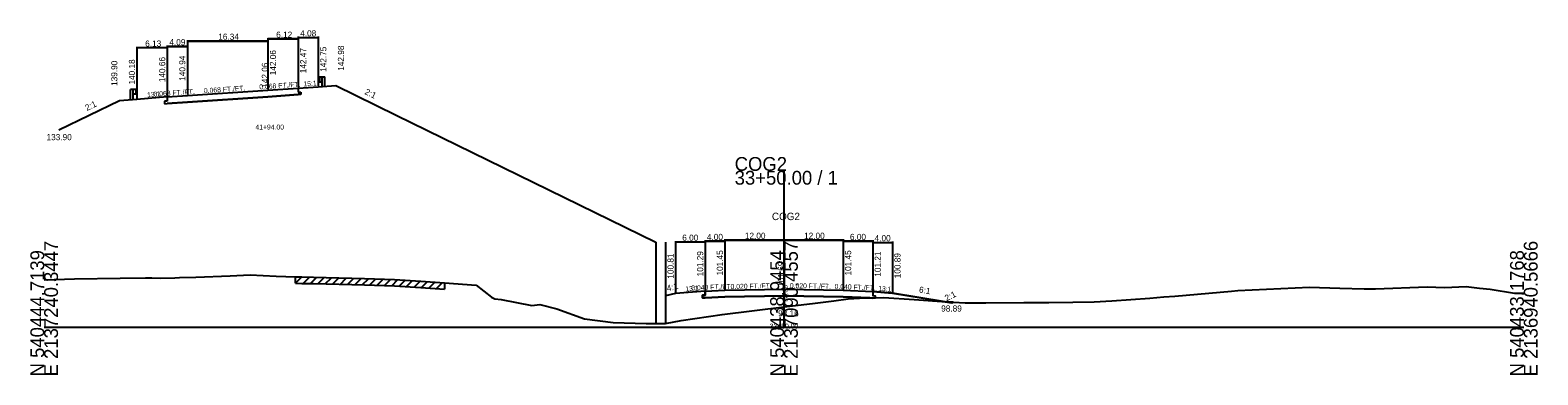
# Model space of a CAD drawing. Extents: x -13397 to 2303, y -10 to 39059.
# Drawn here: x 997.2 to 1302.8, y 6990.3 to 7060.2 of the extents above; entities that cross this region are included whole.
import ezdxf

# ---------------------------------------------------------------- set-up
doc = ezdxf.new("R2010")
doc.units = 0
for name, color, linetype in [('Level 20', 7, 'Continuous'), ('Level 5', 7, 'Continuous'), ('Level 53', 7, 'Continuous'), ('Level 54', 7, 'Continuous'), ('Level 55', 7, 'Continuous'), ('Level 7', 7, 'Continuous'), ('RD_GPK_XS_Cell', 7, 'Continuous'), ('RD_XS_EwShp', 7, 'Continuous'), ('RD_XS_ExGround', 7, 'Continuous'), ('RD_XS_ExPaveRet', 7, 'Continuous'), ('RD_XS_MedBWall', 7, 'Continuous'), ('RD_XS_Pave', 7, 'Continuous'), ('RD_XS_TX_Baseline', 7, 'Continuous'), ('RD_XS_TX_Elev_EX', 7, 'Continuous'), ('RD_XS_TX_Elev_PR', 7, 'Continuous'), ('RD_XS_TX_Station', 7, 'Continuous')]:
    doc.layers.add(name, color=color, linetype=linetype)

msp = doc.modelspace()

# ---------------------------------------------------------------- linework, layer by layer
at = {"layer": 'Level 20'}
for p, q in [((1029.03, 7058.21), (1029.03, 7047.14)), ((1029.03, 7058.21), (1029.03, 7047.14)), ((1029.03, 7058.21), (1029.03, 7047.14)), ((1029.03, 7058.21), (1029.03, 7047.14)), ((1045.37, 7058.62), (1045.37, 7048.26)), ((1045.37, 7058.62), (1045.37, 7048.26)), ((1045.37, 7058.62), (1045.37, 7048.26)), ((1045.37, 7058.42), (1051.5, 7058.42)), ((1051.5, 7058.42), (1045.37, 7058.42)), ((1051.5, 7058.42), (1045.37, 7058.42)), ((1045.37, 7058.21), (1045.37, 7048.26)), ((1045.37, 7058.21), (1045.37, 7048.26)), ((1045.37, 7058.21), (1045.37, 7048.26)), ((1045.37, 7058.21), (1045.37, 7048.26)), ((1051.5, 7058.9), (1051.5, 7048.67)), ((1051.5, 7058.7), (1055.58, 7058.7)), ((1051.5, 7058.62), (1051.5, 7048.67)), ((1051.5, 7058.62), (1051.5, 7048.67)), ((1051.5, 7058.62), (1051.5, 7048.67)), ((1055.58, 7058.9), (1055.58, 7048.95)), ((1018.81, 7056.81), (1018.81, 7046.38)), ((1024.94, 7056.61), (1018.81, 7056.61)), ((1024.94, 7057.09), (1024.94, 7046.86)), ((1024.94, 7057.09), (1024.94, 7046.86)), ((1024.94, 7057.09), (1024.94, 7046.86)), ((1024.94, 7056.89), (1029.03, 7056.89)), ((1024.94, 7056.89), (1029.03, 7056.89)), ((1029.03, 7056.89), (1024.94, 7056.89)), ((1024.94, 7056.81), (1024.94, 7046.86)), ((1029.03, 7058.01), (1045.37, 7058.01)), ((1029.03, 7058.01), (1045.37, 7058.01)), ((1045.37, 7058.01), (1029.03, 7058.01)), ((1045.37, 7058.01), (1029.03, 7058.01)), ((1029.03, 7057.09), (1029.03, 7047.14)), ((1029.03, 7057.09), (1029.03, 7047.14)), ((1029.03, 7057.09), (1029.03, 7047.14)), ((1055.6, 7050.56), (1055.72, 7050.65)), ((1055.6, 7050.46), (1055.72, 7050.37)), ((1055.6, 7050.03), (1055.72, 7050.12)), ((1055.6, 7049.93), (1055.72, 7049.84)), ((1055.73, 7050.66), (1055.8, 7050.67)), ((1055.73, 7050.32), (1055.73, 7050.17)), ((1055.73, 7049.83), (1055.8, 7049.82)), ((1055.8, 7050.73), (1055.8, 7049.76)), ((1055.8, 7050.73), (1056.36, 7050.73)), ((1055.8, 7049.76), (1056.36, 7049.76)), ((1056.36, 7048.75), (1056.36, 7050.73)), ((1056.36, 7050.73), (1056.92, 7050.73)), ((1056.92, 7048.75), (1056.92, 7050.73)), ((1018.81, 7046.18), (1015.24, 7045.9)), ((1017.48, 7046.18), (1017.48, 7048.17)), ((1018.03, 7048.17), (1017.48, 7048.17)), ((1018.03, 7046.18), (1018.03, 7048.17)), ((1018.59, 7048.17), (1018.03, 7048.17)), ((1018.59, 7047.2), (1018.03, 7047.2)), ((1018.59, 7048.17), (1018.59, 7047.2)), ((1018.66, 7048.1), (1018.59, 7048.11)), ((1018.66, 7047.27), (1018.59, 7047.26)), ((1018.66, 7047.76), (1018.66, 7047.61)), ((1018.79, 7048), (1018.68, 7048.09)), ((1018.79, 7047.9), (1018.68, 7047.81)), ((1018.79, 7047.47), (1018.68, 7047.56)), ((1018.79, 7047.37), (1018.68, 7047.28)), ((1024.94, 7046.66), (1018.81, 7046.18)), ((1024.94, 7046.66), (1029.03, 7046.94)), ((1024.94, 7046.66), (1024.94, 7045.83)), ((1029.03, 7046.94), (1045.37, 7048.06)), ((1045.37, 7046.72), (1029.03, 7045.61)), ((1045.37, 7046.72), (1029.03, 7045.61)), ((1029.03, 7045.61), (1045.37, 7046.72)), ((1029.03, 7045.61), (1045.37, 7046.72)), ((1045.37, 7048.06), (1051.5, 7048.47)), ((1051.5, 7047.14), (1045.37, 7046.72)), ((1045.37, 7046.72), (1051.5, 7047.14)), ((1045.37, 7046.72), (1051.5, 7047.14)), ((1051.5, 7048.47), (1055.58, 7048.75)), ((1051.5, 7048.47), (1051.5, 7047.64)), ((1051.5, 7047.64), (1052.01, 7047.67)), ((1052.01, 7047.17), (1051.5, 7047.14)), ((1052.01, 7047.67), (1052.01, 7047.17)), ((1055.58, 7048.75), (1059.15, 7048.98)), ((1059.15, 7048.98), (1071.4, 7042.98)), ((1015.24, 7045.9), (1002.98, 7039.9)), ((1024.94, 7045.83), (1024.43, 7045.8)), ((1024.43, 7045.8), (1024.43, 7045.3)), ((1024.43, 7045.3), (1024.94, 7045.33)), ((1029.03, 7045.61), (1024.94, 7045.33)), ((1029.03, 7045.61), (1024.94, 7045.33)), ((1024.94, 7045.33), (1029.03, 7045.61)), ((1071.4, 7042.98), (1124, 7017.22))]:
    msp.add_line(p, q, dxfattribs=at)
for centre, radius, start, end in [((1055.64, 7050.51), 0.0651, 129.0336, 230.9663), ((1055.64, 7049.98), 0.0651, 129.0336, 230.9663), ((1055.67, 7050.17), 0.0651, 302.9895, 0), ((1055.73, 7050.63), 0.026, 90, 129.0505), ((1055.67, 7050.32), 0.0651, 0, 45), ((1055.73, 7049.86), 0.026, 230.9496, 270), ((1018.66, 7048.07), 0.026, 50.9495, 90), ((1018.72, 7047.76), 0.0651, 135, 180), ((1018.72, 7047.61), 0.0651, 180, 237.0105), ((1018.66, 7047.3), 0.026, 270, 309.0504), ((1018.75, 7047.95), 0.0651, 309.0337, 50.9664), ((1018.75, 7047.42), 0.0651, 309.0337, 50.9664)]:
    msp.add_arc(centre, radius, start, end, dxfattribs=at)
at = {"layer": 'Level 5'}
for p, q in [((1134, 7006.46), (1133.5, 7006.44)), ((1133.5, 7006.44), (1133.5, 7005.94)), ((1134, 7007.29), (1134, 7006.46)), ((1150, 7006.36), (1138, 7006.12)), ((1150, 7006.36), (1138, 7006.12)), ((1150, 7006.36), (1138, 7006.12)), ((1138, 7006.12), (1150, 7006.36)), ((1138, 7006.12), (1150, 7006.36)), ((1162, 7006.12), (1150, 7006.36)), ((1162, 7006.12), (1150, 7006.36)), ((1150, 7006.36), (1162, 7006.12)), ((1150, 7006.36), (1162, 7006.12)), ((1150, 7006.36), (1162, 7006.12)), ((1168, 7007.21), (1168, 7006.38)), ((1168, 7006.38), (1168.5, 7006.36)), ((1168.5, 7006.36), (1168.5, 7005.86)), ((1133.5, 7005.94), (1134, 7005.96)), ((1138, 7006.12), (1134, 7005.96)), ((1138, 7006.12), (1134, 7005.96)), ((1138, 7006.12), (1134, 7005.96)), ((1134, 7005.96), (1138, 7006.12)), ((1168, 7005.88), (1162, 7006.12)), ((1162, 7006.12), (1168, 7005.88)), ((1162, 7006.12), (1168, 7005.88)), ((1162, 7006.12), (1168, 7005.88)), ((1168.5, 7005.86), (1168, 7005.88))]:
    msp.add_line(p, q, dxfattribs=at)
at = {"layer": 'Level 54'}
for p, q in [((1128, 7017.44), (1128, 7007.01)), ((1134, 7017.24), (1128, 7017.24)), ((1134, 7017.6), (1134, 7007.49)), ((1134, 7017.6), (1134, 7007.49)), ((1134, 7017.6), (1134, 7007.49)), ((1134, 7017.6), (1134, 7007.49)), ((1134, 7017.44), (1134, 7007.49)), ((1134, 7017.4), (1138, 7017.4)), ((1134, 7017.4), (1138, 7017.4)), ((1134, 7017.4), (1138, 7017.4)), ((1138, 7017.4), (1134, 7017.4)), ((1138, 7017.84), (1138, 7007.65)), ((1138, 7017.84), (1138, 7007.65)), ((1138, 7017.84), (1138, 7007.65)), ((1138, 7017.84), (1138, 7007.65)), ((1138, 7017.84), (1138, 7007.65)), ((1138, 7017.64), (1150, 7017.64)), ((1138, 7017.64), (1150, 7017.64)), ((1138, 7017.64), (1150, 7017.64)), ((1150, 7017.64), (1138, 7017.64)), ((1150, 7017.64), (1138, 7017.64)), ((1138, 7017.6), (1138, 7007.65)), ((1138, 7017.6), (1138, 7007.65)), ((1138, 7017.6), (1138, 7007.65)), ((1138, 7017.6), (1138, 7007.65)), ((1150, 7017.84), (1150, 7007.89)), ((1150, 7017.84), (1150, 7007.89)), ((1150, 7017.84), (1150, 7007.89)), ((1150, 7017.84), (1150, 7007.89)), ((1150, 7017.84), (1150, 7007.89)), ((1150, 7017.84), (1150, 7007.89)), ((1150, 7017.84), (1150, 7007.89)), ((1150, 7017.84), (1150, 7007.89)), ((1150, 7017.84), (1150, 7007.89)), ((1150, 7017.84), (1150, 7007.89)), ((1150, 7017.64), (1162, 7017.64)), ((1150, 7017.64), (1162, 7017.64)), ((1162, 7017.64), (1150, 7017.64)), ((1162, 7017.64), (1150, 7017.64)), ((1162, 7017.64), (1150, 7017.64)), ((1162, 7017.84), (1162, 7007.65)), ((1162, 7017.84), (1162, 7007.65)), ((1162, 7017.84), (1162, 7007.65)), ((1162, 7017.84), (1162, 7007.65)), ((1162, 7017.84), (1162, 7007.65)), ((1162, 7017.6), (1162, 7007.65)), ((1162, 7017.6), (1162, 7007.65)), ((1162, 7017.6), (1162, 7007.65)), ((1162, 7017.6), (1162, 7007.65)), ((1162, 7017.4), (1168, 7017.4)), ((1168, 7017.4), (1162, 7017.4)), ((1168, 7017.4), (1162, 7017.4)), ((1168, 7017.4), (1162, 7017.4)), ((1168, 7017.6), (1168, 7007.41)), ((1168, 7017.6), (1168, 7007.41)), ((1168, 7017.6), (1168, 7007.41)), ((1168, 7017.6), (1168, 7007.41)), ((1168, 7017.36), (1168, 7007.41)), ((1168, 7017.16), (1172, 7017.16)), ((1172, 7017.36), (1172, 7007.09))]:
    msp.add_line(p, q, dxfattribs=at)
at = {"layer": 'Level 7'}
for p, q in [((1128, 7006.81), (1126, 7006.31)), ((1126, 7006.31), (1126, 7000.71)), ((1134, 7007.29), (1128, 7006.81)), ((1168, 7007.21), (1172, 7006.89)), ((1172, 7006.89), (1184, 7004.89)), ((1184, 7004.89), (1184.27, 7005.03))]:
    msp.add_line(p, q, dxfattribs=at)
at = {"layer": 'RD_GPK_XS_Cell'}
for p, q in [((1150, 7000), (1150, 7031.68)), ((1000, 7000), (1150, 7000)), ((1150, 7000), (1300, 7000))]:
    msp.add_line(p, q, dxfattribs=at)
at = {"layer": 'RD_XS_EwShp'}
for points in [[(1150, 7004.08), (1156.31, 7004.85), (1160.12, 7005.32), (1163.02, 7005.71), (1165.33, 7005.83), (1167.38, 7005.9), (1162, 7006.12), (1150, 7006.36), (1138, 7006.12), (1134, 7005.96), (1133.5, 7005.94), (1133.5, 7006.44), (1134, 7006.46), (1134, 7007.29), (1128, 7006.81), (1126, 7006.31), (1126, 7000.71), (1129.14, 7001.33), (1137.48, 7002.54)], [(1176.42, 7005.6), (1181.99, 7005.15), (1182.66, 7005.11), (1172, 7006.89), (1168, 7007.21), (1168, 7006.38), (1168.5, 7006.36), (1168.5, 7005.94), (1170.24, 7006)], [(1168, 7005.88), (1167.38, 7005.9), (1168.5, 7005.94), (1168.5, 7005.86)], [(1184, 7004.89), (1184.27, 7005.03), (1182.66, 7005.11)]]:
    msp.add_lwpolyline(points, close=True, dxfattribs=at)
at = {"layer": 'RD_XS_ExGround'}
for p, q in [((1000, 7009.61), (1006.16, 7009.81)), ((1006.16, 7009.81), (1015.39, 7009.93)), ((1015.39, 7009.93), (1020.56, 7010.01)), ((1020.56, 7010.01), (1021.8, 7009.98)), ((1021.8, 7009.98), (1023.64, 7009.91)), ((1023.64, 7009.91), (1026.48, 7010.01)), ((1026.48, 7010.01), (1027.47, 7010.03)), ((1027.47, 7010.03), (1030.72, 7010.12)), ((1030.72, 7010.12), (1037.72, 7010.39)), ((1037.72, 7010.39), (1041.79, 7010.56)), ((1041.79, 7010.56), (1047.06, 7010.35)), ((1047.06, 7010.35), (1050.99, 7010.18)), ((1050.99, 7010.18), (1052.23, 7010.16)), ((1052.23, 7010.16), (1054.59, 7010.11)), ((1054.59, 7010.11), (1064.97, 7009.83)), ((1064.97, 7009.83), (1071.06, 7009.67)), ((1071.06, 7009.67), (1076.36, 7009.3)), ((1076.36, 7009.3), (1081.15, 7008.96)), ((1081.15, 7008.96), (1087.57, 7008.47)), ((1087.57, 7008.47), (1090.71, 7006.05)), ((1227.04, 7006.11), (1229.25, 7006.27)), ((1229.25, 7006.27), (1240.71, 7007.3)), ((1240.71, 7007.3), (1242.03, 7007.42)), ((1242.03, 7007.42), (1256.53, 7008.07)), ((1256.53, 7008.07), (1262.67, 7007.89)), ((1262.67, 7007.89), (1267.6, 7007.78)), ((1267.6, 7007.78), (1269.91, 7007.77)), ((1269.91, 7007.77), (1280.38, 7008.19)), ((1280.38, 7008.19), (1283.9, 7008.05)), ((1283.9, 7008.05), (1288.31, 7008.25)), ((1288.31, 7008.25), (1291.04, 7007.92)), ((1291.04, 7007.92), (1293.16, 7007.68)), ((1293.16, 7007.68), (1298.1, 7006.89)), ((1298.1, 7006.89), (1300, 7006.84)), ((1090.71, 7006.05), (1091.39, 7005.74)), ((1091.39, 7005.74), (1092.66, 7005.56)), ((1092.66, 7005.56), (1098.88, 7004.37)), ((1098.88, 7004.37), (1100.47, 7004.58)), ((1100.47, 7004.58), (1103.94, 7003.72)), ((1103.94, 7003.72), (1109.58, 7001.69)), ((1137.48, 7002.54), (1150, 7004.08)), ((1150, 7004.08), (1156.31, 7004.85)), ((1156.31, 7004.85), (1160.12, 7005.32)), ((1160.12, 7005.32), (1163.02, 7005.71)), ((1163.02, 7005.71), (1165.33, 7005.83)), ((1165.33, 7005.83), (1170.24, 7006)), ((1170.24, 7006), (1176.42, 7005.6)), ((1176.42, 7005.6), (1181.99, 7005.15)), ((1181.99, 7005.15), (1186.71, 7004.9)), ((1186.71, 7004.9), (1190.9, 7004.94)), ((1190.9, 7004.94), (1198.65, 7004.99)), ((1198.65, 7004.99), (1203.68, 7004.99)), ((1203.68, 7004.99), (1208.58, 7005.03)), ((1208.58, 7005.03), (1212.86, 7005.1)), ((1212.86, 7005.1), (1216.46, 7005.31)), ((1216.46, 7005.31), (1224.16, 7005.88)), ((1224.16, 7005.88), (1227.04, 7006.11)), ((1109.58, 7001.69), (1115.38, 7000.93)), ((1115.38, 7000.93), (1122.05, 7000.7)), ((1122.05, 7000.7), (1125.99, 7000.71)), ((1125.99, 7000.71), (1129.14, 7001.33)), ((1129.14, 7001.33), (1137.48, 7002.54))]:
    msp.add_line(p, q, dxfattribs=at)
at = {"layer": 'RD_XS_ExPaveRet'}
for p, q in [((1050.99, 7008.88), (1050.99, 7010.18)), ((1050.99, 7008.88), (1052.27, 7010.16)), ((1052.49, 7008.85), (1053.77, 7010.13)), ((1053.99, 7008.82), (1055.26, 7010.09)), ((1055.49, 7008.78), (1056.76, 7010.05)), ((1056.99, 7008.74), (1058.26, 7010.01)), ((1058.49, 7008.7), (1059.76, 7009.97)), ((1059.99, 7008.66), (1061.26, 7009.93)), ((1061.49, 7008.63), (1062.76, 7009.89)), ((1062.99, 7008.59), (1064.26, 7009.85)), ((1064.49, 7008.55), (1065.76, 7009.81)), ((1065.99, 7008.51), (1067.26, 7009.77)), ((1067.49, 7008.47), (1068.76, 7009.73)), ((1068.99, 7008.43), (1070.26, 7009.69)), ((1070.49, 7008.39), (1071.73, 7009.62)), ((1071.99, 7008.31), (1073.21, 7009.52)), ((1073.49, 7008.2), (1074.71, 7009.42)), ((1074.99, 7008.1), (1076.21, 7009.32)), ((1050.99, 7008.88), (1052.23, 7008.86)), ((1052.23, 7008.86), (1054.59, 7008.81)), ((1054.59, 7008.81), (1064.97, 7008.53)), ((1064.97, 7008.53), (1071.06, 7008.37)), ((1071.06, 7008.37), (1076.36, 7008)), ((1076.36, 7008), (1081.15, 7007.66)), ((1076.49, 7008), (1077.71, 7009.21)), ((1078, 7007.89), (1079.21, 7009.1)), ((1079.5, 7007.78), (1080.71, 7008.99)), ((1081.15, 7008.96), (1081.15, 7007.66))]:
    msp.add_line(p, q, dxfattribs=at)
at = {"layer": 'RD_XS_MedBWall'}
for p, q in [((1124, 7017.22), (1124, 7000.7)), ((1126, 7017.22), (1126, 7006.31))]:
    msp.add_line(p, q, dxfattribs=at)
at = {"layer": 'RD_XS_Pave'}
for p, q in [((1134, 7007.29), (1138, 7007.45)), ((1138, 7007.45), (1150, 7007.69)), ((1150, 7007.69), (1162, 7007.45)), ((1162, 7007.45), (1168, 7007.21))]:
    msp.add_line(p, q, dxfattribs=at)

# ---------------------------------------------------------------- texts
at = {"layer": 'Level 20'}
for s, height, p in [('4.09', 1.25, (1025.38, 7057.14)), ('4.09', 1.25, (1025.38, 7057.14)), ('4.09', 1.25, (1025.38, 7057.14)), ('16.34', 1.25, (1035.3, 7058.26)), ('16.34', 1.25, (1035.3, 7058.26)), ('16.34', 1.25, (1035.3, 7058.26)), ('16.34', 1.25, (1035.3, 7058.26)), ('6.12', 1.25, (1047.04, 7058.67)), ('6.12', 1.25, (1047.04, 7058.67)), ('6.12', 1.25, (1047.04, 7058.67)), ('4.08', 1.25, (1051.91, 7058.95)), ('6.13', 1.25, (1020.48, 7056.86)), ('41+94.00', 1, (1042.83, 7040.06)), ('133.90', 1.25, (1000.48, 7037.9))]:
    msp.add_text(s, height=height, dxfattribs=at).set_placement(p)
for s, height, rotation, p in [('142.06', 1.25, 90, (1047.02, 7051.06)), ('142.06', 1.25, 90, (1047.02, 7051.06)), ('142.47', 1.25, 90, (1053.14, 7051.47)), ('142.75', 1.25, 90, (1057.22, 7051.75)), ('142.98', 1.25, 90, (1060.8, 7051.98)), ('139.90', 1.25, 90, (1014.84, 7048.9)), ('140.18', 1.25, 90, (1018.42, 7049.18)), ('140.66', 1.25, 90, (1024.55, 7049.66)), ('140.94', 1.25, 90, (1028.63, 7049.94)), ('140.94', 1.25, 90, (1028.63, 7049.94)), (' 142.06', 1.25, 90, (1045.37, 7048.06)), ('0.068 FT./FT.', 1, 3.9032, (1043.65, 7048.19)), ('0.068 FT./FT.', 1, 3.9032, (1043.65, 7048.19)), ('0.068 FT./FT.', 1, 3.9032, (1043.65, 7048.19)), ('15:1', 1, 3.8242, (1052.59, 7048.8)), ('13:1', 1, 4.4772, (1020.91, 7046.6)), ('0.068 FT./FT.', 1, 3.8951, (1022.21, 7046.73)), ('0.068 FT./FT.', 1, 3.8951, (1022.21, 7046.73)), ('0.068 FT./FT.', 1, 3.8951, (1022.21, 7046.73)), ('0.068 FT./FT.', 1, 3.899, (1032.42, 7047.42)), ('0.068 FT./FT.', 1, 3.899, (1032.42, 7047.42)), ('0.068 FT./FT.', 1, 3.899, (1032.42, 7047.42)), ('0.068 FT./FT.', 1, 3.899, (1032.42, 7047.42)), ('2:1', 1.25, 333.9018, (1064.87, 7047.3)), ('2:1', 1.25, 26.0762, (1008.67, 7043.8))]:
    msp.add_text(s, height=height, rotation=rotation, dxfattribs=at).set_placement(p)
at = {"layer": 'Level 53'}
for s, rotation, p in [('101.45', 90, (1137.62, 7010.45)), ('101.45', 90, (1137.62, 7010.45)), ('101.45', 90, (1137.62, 7010.45)), ('101.45', 90, (1163.62, 7010.45)), ('101.45', 90, (1163.62, 7010.45)), ('101.45', 90, (1163.62, 7010.45)), ('100.81', 90, (1127.62, 7009.81)), ('101.29', 90, (1133.62, 7010.29)), ('101.21', 90, (1169.62, 7010.21)), ('100.89', 90, (1173.62, 7009.89)), ('4:1', 14.0362, (1126.39, 7007.21)), ('6:1', 350.5377, (1177.3, 7007.02))]:
    msp.add_text(s, height=1.25, rotation=rotation, dxfattribs=at).set_placement(p)
for s, p in [('98.16', (1148.8, 7002.16)), ('98.89', (1181.87, 7003.14))]:
    msp.add_text(s, height=1.25, dxfattribs=at).set_placement(p)
at = {"layer": 'Level 54'}
for s, p in [('6.00', (1129.37, 7017.49)), ('4.00', (1134.37, 7017.65)), ('4.00', (1134.37, 7017.65)), ('4.00', (1134.37, 7017.65)), ('4.00', (1134.37, 7017.65)), ('12.00', (1142.07, 7017.89)), ('12.00', (1142.07, 7017.89)), ('12.00', (1142.07, 7017.89)), ('12.00', (1142.07, 7017.89)), ('12.00', (1142.07, 7017.89)), ('12.00', (1154.07, 7017.89)), ('12.00', (1154.07, 7017.89)), ('12.00', (1154.07, 7017.89)), ('12.00', (1154.07, 7017.89)), ('12.00', (1154.07, 7017.89)), ('6.00', (1163.37, 7017.65)), ('6.00', (1163.37, 7017.65)), ('6.00', (1163.37, 7017.65)), ('6.00', (1163.37, 7017.65)), ('4.00', (1168.37, 7017.41))]:
    msp.add_text(s, height=1.25, dxfattribs=at).set_placement(p)
at = {"layer": 'Level 55'}
for s, height, rotation, p in [('13:1', 1, 4.5739, (1130.03, 7007.22)), ('0.040 FT./FT.', 1, 2.2906, (1131.22, 7007.43)), ('0.040 FT./FT.', 1, 2.2906, (1131.22, 7007.43)), ('0.040 FT./FT.', 1, 2.2906, (1131.22, 7007.43)), ('0.040 FT./FT.', 1, 2.2906, (1131.22, 7007.43)), ('0.020 FT./FT.', 1, 1.1458, (1139.17, 7007.72)), ('0.020 FT./FT.', 1, 1.1458, (1139.17, 7007.72)), ('0.020 FT./FT.', 1, 1.1458, (1139.17, 7007.72)), ('0.020 FT./FT.', 1, 1.1458, (1139.17, 7007.72)), ('0.020 FT./FT.', 1, 1.1458, (1139.17, 7007.72)), ('0.020 FT./FT.', 1, 358.8542, (1151.18, 7007.92)), ('0.020 FT./FT.', 1, 358.8542, (1151.18, 7007.92)), ('0.020 FT./FT.', 1, 358.8542, (1151.18, 7007.92)), ('0.020 FT./FT.', 1, 358.8542, (1151.18, 7007.92)), ('0.020 FT./FT.', 1, 358.8542, (1151.18, 7007.92)), ('0.040 FT./FT.', 1, 357.7094, (1160.24, 7007.77)), ('0.040 FT./FT.', 1, 357.7094, (1160.24, 7007.77)), ('0.040 FT./FT.', 1, 357.7094, (1160.24, 7007.77)), ('0.040 FT./FT.', 1, 357.7094, (1160.24, 7007.77)), ('13:1', 1, 355.4261, (1169.07, 7007.38)), ('2:1', 1.25, 26.5651, (1182.96, 7005.21))]:
    msp.add_text(s, height=height, rotation=rotation, dxfattribs=at).set_placement(p)
at = {"layer": 'RD_GPK_XS_Cell'}
for s, p in [('COG2', (1140, 7031.68)), ('33+50.00 / 1', (1140, 7028.88))]:
    msp.add_text(s, height=2.8, dxfattribs=at).set_placement(p)
for s, p in [('N 540444.7139', (1000, 6990)), ('E 2137240.3447', (1002.8, 6990)), ('N 540438.9454', (1150, 6990)), ('E 2137090.4557', (1152.8, 6990)), ('N 540433.1768', (1300, 6990)), ('E 2136940.5666', (1302.8, 6990))]:
    msp.add_text(s, height=2.8, rotation=90, dxfattribs=at).set_placement(p)
at = {"layer": 'RD_XS_TX_Baseline'}
msp.add_text('COG2', height=1.5, dxfattribs=at).set_placement((1147.55, 7021.69))
at = {"layer": 'RD_XS_TX_Elev_EX'}
msp.add_text('98.08', height=1, rotation=90, dxfattribs=at).set_placement((1150.75, 7005.08))
at = {"layer": 'RD_XS_TX_Elev_PR'}
msp.add_text(' 101.69', height=1.25, rotation=90, dxfattribs=at).set_placement((1150, 7007.69))
at = {"layer": 'RD_XS_TX_Station'}
msp.add_text('33+50.00', height=1, dxfattribs=at).set_placement((1147.1, 6999.69))

doc.saveas('drawing.dxf')
